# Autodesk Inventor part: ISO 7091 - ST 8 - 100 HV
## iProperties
IsCustomPart: 0
Created: 2007-11
Part Number: ISO 7091 - ST 8 - 100 HV
Material: Steel
Description: Plain washers - Normal series - Product grade C
Document SubType Name: Modeling
Standard: ISO 7091
Designer: CM
Standard Revision: Second edition 2000-06-01
Standards Organization: ISO
Language: en-US
Size Designation: ST 8 - 100 HV
Categories: <MemberInstance><Categories><Category DisplayName="Fasteners" InternalName="e4da775c-781d-43d5-af7c-5136215cf5a6" Mnemonic="FSTN"><Category DisplayName="Washers
Density: 7.85 g/cm^3
Mass: 1.72631 g
Surface Area: 4.00553 cm^2
Volume: 0.219911 cm^3
Author: CM
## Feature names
1. Body [Extrusion]
